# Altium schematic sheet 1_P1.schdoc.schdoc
size 309 x 223 mm; Symbol: Sheet-Symbol_A4; Device: Sheet-Symbol_A4; Company: 嘉立创EDA; Version: V1.0; Page Size: A4; @Project Name: 20240125_无人机探照灯_12; @Page Count: 1; @Update Date: 2024-03-27; @Create Date: 2024-03-25; @Schematic Name: schematic1; @Page No: 1; @Page Name: P1
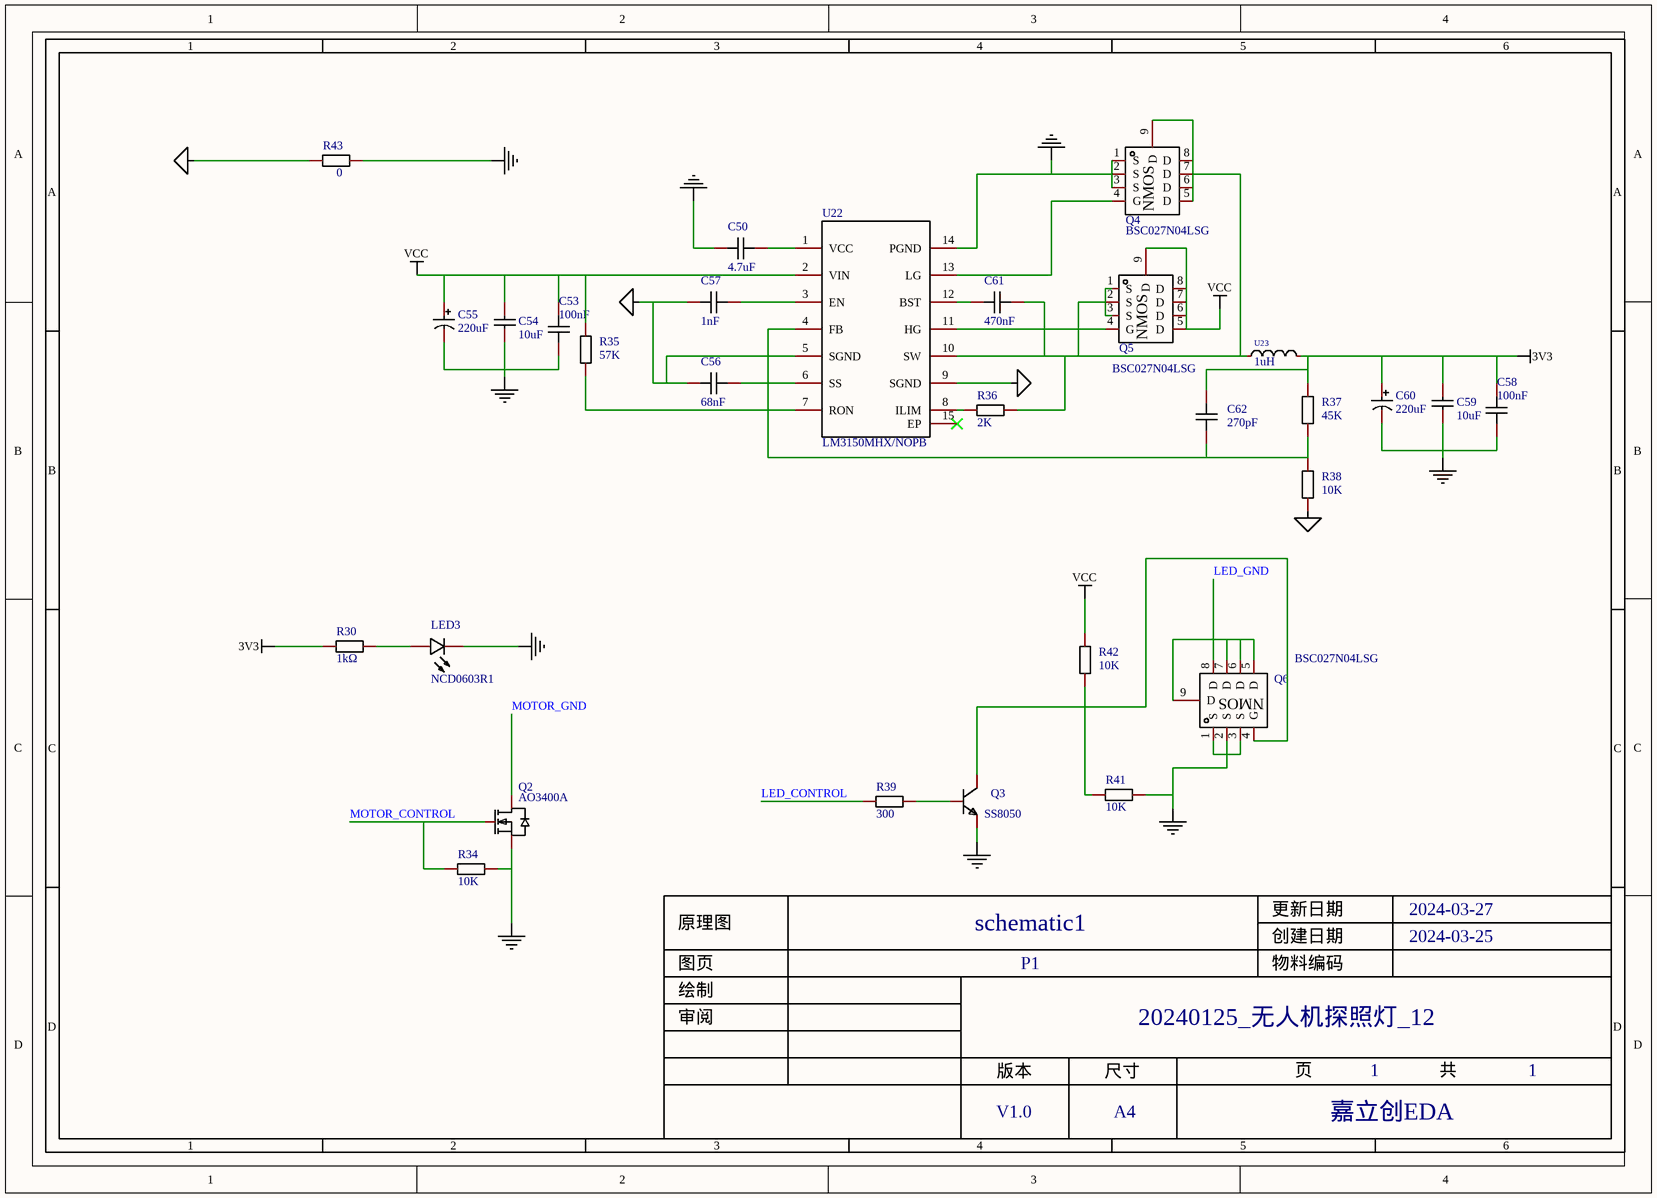
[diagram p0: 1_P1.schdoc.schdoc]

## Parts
C50  4.7uF  [C0603]
C53  100nF  [C0603]
C54  10uF  [C1206]
C55  220uF  [CAP-TH_BD8.0-P3.50-D0.6-FD]
C56  68nF  [C0603]
C57  1nF  [C0603]
C58  100nF  [C0603]
C59  10uF  [C1206]
C60  220uF  [CAP-TH_BD8.0-P3.50-D0.6-FD]
C61  470nF  [C0603]
C62  270pF  [C0603]
LED3  NCD0603R1  [LED0603-RD_RED]
Q2  AO3400A  [SOT-23-3_L2.9-W1.3-P1.90-LS2.4-BR]
Q3  SS8050  [SOT-23-3_L2.9-W1.3-P1.90-LS2.4-BR]
Q4  BSC027N04LSG  [PG-TDSON-8_L5.0-W6.0-P1.27-LS6.2-BL-EP]
Q5  BSC027N04LSG  [PG-TDSON-8_L5.0-W6.0-P1.27-LS6.2-BL-EP]
Q6  BSC027N04LSG  [PG-TDSON-8_L5.0-W6.0-P1.27-LS6.2-BL-EP]
R30  1kΩ  [R0603]
R34  10K  [R0603]
R35  57K  [R0603]
R36  2K  [R0603]
R37  45K  [R0603]
R38  10K  [R0603]
R39  300  [R0603]
R41  10K  [R0603]
R42  10K  [R0603]
R43  0  [R0603]
U22  LM3150MHX/NOPB  [HTSSOP-14_L5.0-W4.4-P0.65-LS6.4-BL-EP]
U23  1uH  [IND-SMD_L12.8-W12.8_B953AS]

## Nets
3V3: C58.2 C59.2 C60.1 C62.1 R30.2 R37.2 U23.2
NetC50_1: C50.1 C53.1 C54.1 C55.2 C56.1 C57.1 C58.1 C59.1 C60.2 LED3.1(K) Q2.2(S) Q3.2(E) Q4.1(S) Q4.2(S) Q4.3(S) Q6.1(S) Q6.2(S) Q6.3(S) R34.2 R38.1 R41.2 R43.1 R43.2 U22.5(SGND) U22.9(SGND) U22.14(PGND)
VCC: C53.2 C54.2 C55.1 Q5.5(D) Q5.6(D) Q5.7(D) Q5.8(D) Q5.9(D) R35.2 R42.2 U22.2(VIN)
LED_CONTROL: R39.1
LED_GND: Q6.5(D) Q6.6(D) Q6.7(D) Q6.8(D) Q6.9(D)
MOTOR_CONTROL: Q2.1(G) R34.1
MOTOR_GND: Q2.3(D)
NetC50_2: C50.2 U22.1(VCC)
NetC56_2: C56.2 U22.6(SS)
NetC57_2: C57.2 U22.3(EN)
NetC61_1: C61.1 U22.12(BST)
NetC61_2: C61.2 Q4.5(D) Q4.6(D) Q4.7(D) Q4.8(D) Q4.9(D) Q5.1(S) Q5.2(S) Q5.3(S) R36.2 U22.10(SW) U23.1
NetC62_2: C62.2 R37.1 R38.2 U22.4(FB)
NetLED3_2: LED3.2(A) R30.1
NetQ3_1: Q3.1(B) R39.2
NetQ3_3: Q3.3(C) Q6.4(G) R41.1 R42.1
NetQ4_4: Q4.4(G) U22.13(LG)
NetQ5_4: Q5.4(G) U22.11(HG)
NetR35_1: R35.1 U22.7(RON)
NetR36_1: R36.1 U22.8(ILIM)

Not connected (* = marked no-connect by the designer): U22 15(EP)*

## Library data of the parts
C50 C53 C56-C58 C61 C62 = CAP_0603: Symbol: CapAcitance; Convert to PCB: yes
C54 C59 = CL31A106KBHNNNE: Manufacturer: SAMSUNG(三星); Add into BOM: yes; Tolerance: ±10%; Voltage Rated: 50V; Temperature Coefficient: X5R; Description: 容值:10uF;精度:±10%;额定电压:50V;材质(温度系数):X5R;
C55 C60 = KM227M035F12RR0VH2FP0: Manufacturer: CX(承兴); Symbol: 220uf/35V; Add into BOM: yes; Tolerance: ±20%; Rated Voltage: 35V; φD: 8mm; L: 12mm; Lifetime @ Temp: 2000hrs@105℃; Description: 容值:220uF;精度:±20%;额定电压:35V;纹波电流:-;等效串联电阻:-;
LED3 = NCD0603R1_C84263: Manufacturer: 国星光电; Symbol: FC-DA1608HRK-620D; Add into BOM: yes; Emitted Color: 红灯; Description: 发光颜色:红灯;
Q2 = AO3400A_C347475: Manufacturer: UMW(友台半导体); Add into BOM: yes; Type: N沟道; Drain Source Voltage (Vdss): 30V; Continuous Drain Current (Id): 5.8A; Power Dissipation (Pd): 1.4W; Drain Source On Resistance (RDS(on)@Vgs,Id): 35mΩ@10V,5.8A; Gate Threshold Voltage (Vgs(th)@Id): 1.4V@250uA; Total Gate Charge (Qg@Vgs): 12nC@4.5V; Input Capacitance (Ciss@Vds): 1.05nF@15V; Description: 类型:N沟道;漏源电压(Vdss):30V;连续漏极电流(Id):5.8A;功率(Pd):1.4W;导通电阻(RDS(on)@Vgs,Id):35mΩ@10V,5.8A;阈值电压(Vgs(th)@Id):1.4V@250uA;
Q3 = SS8050_C2150: Manufacturer: CJ(江苏长电/长晶); Add into BOM: yes; Transistor Type: NPN; Collector Current (Ic): 1.5A; Collector-Emitter Breakdown Voltage (Vceo): 25V; Power Dissipation (Pd): 300mW; DC Current Gain (hFE@Ic,Vce): 200@100mA,1V; Transition Frequency (fT): 100MHz; Collector Cut-Off Current (Icbo): 100nA; Collector-Emitter Saturation Voltage (VCE(sat)@Ic,Ib): 500mV@800mA,80mA; Description: 晶体管类型:NPN;集电极电流(Ic):1.5A;集射极击穿电压(Vceo):25V;功率(Pd):300mW;直流电流增益(hFE@Ic,Vce):200@100mA,1V;
Q4-Q6 = BSC027N04LSG: Manufacturer: Infineon(英飞凌); Add into BOM: yes; Description: 类型:-;漏源电压(Vdss):-;连续漏极电流(Id):-;功率(Pd):-;导通电阻(RDS(on)@Vgs,Id):-;阈值电压(Vgs(th)@Id):-;
R30 = 0603WAF1001T5E: Manufacturer: UNI-ROYAL(厚声); Add into BOM: yes; Tolerance: ±1%; Power(Watts): 100mW; Temperature Coefficient: ±100ppm/℃; Overload Voltage (Max): 75V; Description: 电阻类型:厚膜电阻;阻值:1kΩ;精度:±1%;功率:100mW;
R34-R39 R41-R43 = Res_0603: Symbol: 电阻; Convert to PCB: yes
U22 = LM3150MHX/NOPB: Manufacturer: TI(德州仪器); Add into BOM: yes; Function: 降压型; Input Voltage: 6V~42V; Output Current (Max): 12A; Switching Frequency: 1MHz; Synchronous Rectification: 是; Number of Outputs: 1; Topology: 降压式; Description: 功能类型:降压型;输入电压:6V~42V;输出电流(最大值):12A;
U23 = B82477G4102M000: Manufacturer: TDK; Add into BOM: yes; Tolerance: ±20%; Rated Current: 9.8A; Saturation Current (Isat): 15A; DC Resistance (DCR): 7mΩ; Description: 电感值:1uH;精度:±20%;额定电流:9.8A;饱和电流(Isat):15A;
